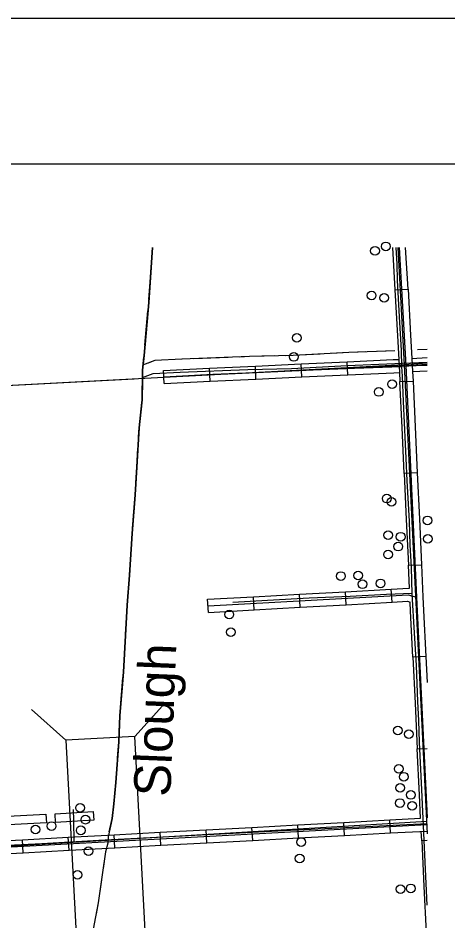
# Model space of a CAD drawing. Extents: x 646058 to 725608, y 1473014 to 1561048.
# Drawn here: x 666031 to 668499, y 1555862 to 1561048 of the extents above; entities that cross this region are included whole.
import ezdxf

# ---------------------------------------------------------------- set-up
doc = ezdxf.new("R2010")
doc.units = 0
for name, color, linetype in [('Default', 7, 'Continuous'), ('R_Border Notes', 7, 'Continuous'), ('T_Vehicle Path Rt', 7, 'Continuous')]:
    doc.layers.add(name, color=color, linetype=linetype)

msp = doc.modelspace()

# ---------------------------------------------------------------- linework, layer by layer
at = {"layer": 'Default'}
for p, q in [((668194.9, 1559486.8), (668269.8, 1559491.1)), ((667133.3, 1558962.1), (667129.8, 1559037)), ((667397, 1558974.4), (667393.5, 1559049.3)), ((667660.7, 1558986.8), (667657.2, 1559061.7)), ((667924.4, 1558999.1), (667920.9, 1559074)), ((666869.6, 1558949.7), (666866.1, 1559024.6)), ((668223.8, 1558960), (668298.7, 1558963.5)), ((668322.9, 1558436), (668248, 1558432.6)), ((668272.3, 1557905.1), (668347.2, 1557908.6)), ((667650.9, 1557664), (667646.7, 1557738.9)), ((667914.5, 1557678.7), (667910.3, 1557753.6)), ((668178.1, 1557693.4), (668173.9, 1557768.2)), ((667123.7, 1557634.7), (667119.5, 1557709.6)), ((667387.3, 1557649.4), (667383.1, 1557724.2)), ((668372.2, 1557381.3), (668297.3, 1557377.7)), ((666701.1, 1556921.1), (666877.5, 1557117.5)), ((666305.7, 1556899.8), (666109.2, 1557076.2)), ((668322.8, 1556850.3), (668379.5, 1556853)), ((668322.8, 1556850.3), (668322.8, 1556850.3)), ((668168.9, 1556367.5), (668164.9, 1556442.4)), ((667114.5, 1556310.9), (667110.4, 1556385.8)), ((667378.1, 1556325), (667374.1, 1556399.9)), ((667641.7, 1556339.2), (667637.7, 1556414.1)), ((667905.3, 1556353.3), (667901.3, 1556428.2)), ((666060, 1556254.2), (666056, 1556329.1)), ((666323.6, 1556268.4), (666319.6, 1556343.3)), ((666587.2, 1556282.6), (666583.2, 1556357.5)), ((666850.8, 1556296.7), (666846.8, 1556371.6)), ((668379.5, 1556324.4), (668348.4, 1556322.9))]:
    msp.add_line(p, q, dxfattribs=at)
for points in [[(666554.7, 1556373.2), (666570.9, 1556451.2), (666581.9, 1556534.9), (666592.8, 1556657.2), (666609.5, 1556891.6), (666615.4, 1557042.4), (666635.7, 1557290.6), (666647.4, 1557501.1), (666658.3, 1557675.8), (666671.4, 1557848.4), (666686, 1558087.9), (666704.2, 1558310.7), (666713.6, 1558469.4), (666726, 1558693.7), (666743.5, 1558855.3), (666745.7, 1558968.2), (666745.7, 1559025), (666754.4, 1559110.1), (666781.3, 1559413.7), (666802.2, 1559731.1)], [(666802.2, 1559731.1), (666781.3, 1559413.7), (666754.4, 1559110.1), (666745.7, 1559025), (666745.7, 1558968.2), (666743.5, 1558855.3), (666726, 1558693.7), (666713.6, 1558469.4), (666704.2, 1558310.7), (666686, 1558087.9), (666671.4, 1557848.4), (666658.3, 1557675.8), (666647.4, 1557501.1), (666635.7, 1557290.6), (666615.4, 1557042.4), (666609.5, 1556891.6), (666592.8, 1556657.2), (666581.9, 1556534.9), (666570.9, 1556451.2)], [(666789, 1559530.9), (666802.2, 1559731.1)], [(668181.1, 1559731.1), (668194.9, 1559486.8)], [(668235, 1559044.3), (668231.9, 1559138.2), (668220.4, 1559331.5), (668209.5, 1559543.3), (668208.1, 1559634.4), (668202, 1559731.1)], [(668211.1, 1559731.1), (668247.5, 1559057.2)], [(668218.7, 1559731.1), (668257.1, 1559052.2), (668318.2, 1557722), (668379.5, 1556455.4)], [(668269.8, 1559491.1), (668256.2, 1559731.1)], [(666782.5, 1559432.1), (666789, 1559530.9)], [(668194.9, 1559486.8), (668209.8, 1559223.3)], [(668269.8, 1559491.1), (668284.7, 1559227.5)], [(666759.6, 1559169.1), (666777.1, 1559366.4)], [(668209.8, 1559223.3), (668217.5, 1559087.9), (668221.3, 1559013)], [(668284.7, 1559227.5), (668292.4, 1559092.2), (668296.2, 1559017.3)], [(668193.4, 1559137.5), (667930.5, 1559126.7), (667610.5, 1559110.2), (667359.8, 1559103.6), (666972.1, 1559088.7), (666817.1, 1559080.5), (666745.7, 1559053.7)], [(668028.6, 1559130.7), (667930.5, 1559126.7), (667830.8, 1559121.6)], [(668193.4, 1559137.5), (668094.5, 1559133.4)], [(668379.5, 1559145.4), (668324, 1559142.9)], [(668379.5, 1559145.4), (668324, 1559142.9)], [(666744.4, 1558905.8), (666745.7, 1558968.2), (666745.7, 1559025), (666753.7, 1559103.4)], [(666973.4, 1559088.8), (666972.1, 1559088.7), (666817.1, 1559080.5), (666778.3, 1559065.9)], [(667237.2, 1559098.9), (667039.4, 1559091.3)], [(667501.1, 1559107.3), (667359.8, 1559103.6), (667303.2, 1559101.4)], [(667764.9, 1559118.2), (667610.5, 1559110.2), (667567.1, 1559109.1)], [(667920.9, 1559074), (668184.6, 1559086.4)], [(668184.6, 1559086.4), (668217.5, 1559087.9)], [(668292.4, 1559092.2), (668379.5, 1559098)], [(668247.5, 1559057.2), (665595.2, 1558916.1)], [(666745.7, 1558983.3), (666807.2, 1559006.4), (666962.3, 1559014.6), (667349.9, 1559029.5), (667600.6, 1559036.1), (667920.7, 1559052.6), (668283.5, 1559067.4), (668379.5, 1559071.7)], [(666866.1, 1559024.6), (667129.8, 1559037)], [(666867.8, 1558987.2), (668257.1, 1559052.2), (668379.5, 1559060.4)], [(666905.1, 1558990), (667149.2, 1559002.4), (667432.7, 1559014.9), (667630.3, 1559023.1), (667963.5, 1559036.6), (668176.6, 1559045.9), (668235, 1559046)], [(667129.8, 1559037), (667393.5, 1559049.3)], [(667393.5, 1559049.3), (667657.2, 1559061.7)], [(667657.2, 1559061.7), (667920.9, 1559074)], [(668379.5, 1559053.1), (668315.7, 1559050.8), (668235, 1559046)], [(668294.5, 1557739.8), (668289.8, 1557894.2), (668282.8, 1558022.7), (668277.7, 1558159), (668264.1, 1558390.2), (668259, 1558521.3), (668255.3, 1558600.5), (668243.7, 1558846.7), (668238.6, 1558990.8), (668235, 1559044.3)], [(668379.5, 1559065.9), (668247.5, 1559057.2)], [(668247.5, 1559057.2), (668379.5, 1556362.3)], [(666698.3, 1558974.8), (665669.9, 1558920.1)], [(667133.3, 1558962.1), (667397, 1558974.4)], [(667397, 1558974.4), (667660.7, 1558986.8)], [(667660.7, 1558986.8), (667924.4, 1558999.1)], [(667924.4, 1558999.1), (668188.1, 1559011.5)], [(668188.1, 1559011.5), (668221.3, 1559013)], [(668221.3, 1559013), (668223.8, 1558960)], [(668296.2, 1559017.3), (668379.5, 1559022.8)], [(668296.2, 1559017.3), (668298.7, 1558963.5)], [(666869.6, 1558949.7), (667133.3, 1558962.1)], [(668235.9, 1558696.3), (668223.8, 1558960)], [(668298.7, 1558963.5), (668310.8, 1558699.8)], [(666723.2, 1558642.9), (666726, 1558693.7), (666741.8, 1558839.9)], [(668248, 1558432.6), (668235.9, 1558696.3)], [(668310.8, 1558699.8), (668322.9, 1558436)], [(666708.2, 1558379.3), (666713.6, 1558469.4), (666719.6, 1558577)], [(668248, 1558432.6), (668260.1, 1558168.9)], [(668322.9, 1558436), (668335.1, 1558172.3)], [(666688.3, 1558116.1), (666704.2, 1558310.7), (666704.3, 1558313.4)], [(668260.1, 1558168.9), (668272.3, 1557905.1)], [(668335.1, 1558172.3), (668347.2, 1557908.6)], [(666677.7, 1557951.4), (666683.7, 1558050.2)], [(666671.7, 1557852.6), (666677.7, 1557951.4)], [(668278.4, 1557772.8), (668272.3, 1557905.1)], [(668347.2, 1557908.6), (668355.7, 1557723.8), (668359.5, 1557645)], [(666652.9, 1557589.3), (666658.3, 1557675.8), (666666.7, 1557786.8)], [(667121.6, 1557672.1), (668270.4, 1557736.1), (668318.2, 1557722)], [(667263.7, 1557693.5), (667462.6, 1557705), (667702.2, 1557717.6), (667937.6, 1557728), (668145.8, 1557739.5), (668294.4, 1557744.8)], [(667383.1, 1557724.2), (667646.7, 1557738.9)], [(667646.7, 1557738.9), (667910.3, 1557753.6)], [(667910.3, 1557753.6), (668173.9, 1557768.2)], [(668173.9, 1557768.2), (668274.8, 1557773.9), (668278.4, 1557772.8)], [(668379.5, 1555953.1), (668349.2, 1556616.2), (668336.7, 1556890), (668331.1, 1557013), (668326.1, 1557122.8), (668317.8, 1557328.6), (668306.9, 1557517.5), (668294.5, 1557739.8)], [(667119.5, 1557709.6), (667383.1, 1557724.2)], [(667650.9, 1557664), (667914.5, 1557678.7)], [(667914.5, 1557678.7), (668178.1, 1557693.4)], [(668178.1, 1557693.4), (668266.1, 1557698.3), (668282.1, 1557693.6)], [(668284.6, 1557641.3), (668282.1, 1557693.6)], [(667123.7, 1557634.7), (667387.3, 1557649.4)], [(667387.3, 1557649.4), (667650.9, 1557664)], [(668297.3, 1557377.7), (668284.6, 1557641.3)], [(668359.5, 1557645), (668372.2, 1557381.3)], [(666637.7, 1557325.7), (666647.4, 1557501.1), (666648.8, 1557523.4)], [(668297.3, 1557377.7), (668310.1, 1557114)], [(668372.2, 1557381.3), (668379.5, 1557232.1)], [(666617, 1557062.5), (666633.2, 1557259.9)], [(668310.1, 1557114), (668322.8, 1556850.3)], [(666602.9, 1556798.9), (666609.5, 1556891.6), (666613.6, 1556996.6)], [(668335.6, 1556586.6), (668322.8, 1556850.3)], [(666581.9, 1556535.8), (666592.8, 1556657.2), (666598.2, 1556733.1)], [(668342.1, 1556451.9), (668335.6, 1556586.6)], [(666347.4, 1556501.5), (666349.4, 1556440.1), (666350.6, 1556316)], [(665732.9, 1556278.3), (668379.5, 1556436.3)], [(666570.9, 1556451.2), (666549.1, 1556346.3), (666546.9, 1556309.9), (666533.8, 1556258.9), (666514.9, 1556126.4), (666490.1, 1555965.5), (666447.9, 1555734)], [(666554.7, 1556373.2), (666570.9, 1556451.2), (666573.4, 1556470.3)], [(667901.3, 1556428.2), (668164.9, 1556442.4)], [(668164.9, 1556442.4), (668342.1, 1556451.9)], [(664476.5, 1556202.7), (665741.1, 1556274.7), (668379.5, 1556416.3)], [(668379.5, 1556420.5), (667910.2, 1556396.6), (667595.5, 1556382.7), (667045.2, 1556354), (666678, 1556333.2), (666494.9, 1556324.3), (666168.3, 1556305.5), (666010.9, 1556296.6), (665815, 1556286.7), (665717.8, 1556282.3)], [(666846.8, 1556371.6), (667110.4, 1556385.8)], [(667110.4, 1556385.8), (667374.1, 1556399.9)], [(667374.1, 1556399.9), (667637.7, 1556414.1)], [(667637.7, 1556414.1), (667901.3, 1556428.2)], [(668358.2, 1556419.4), (668379.5, 1556421.1)], [(665776.5, 1556314.1), (666056, 1556329.1)], [(666056, 1556329.1), (666319.6, 1556343.3)], [(666319.6, 1556343.3), (666583.2, 1556357.5)], [(666583.2, 1556357.5), (666846.8, 1556371.6)], [(667378.1, 1556325), (667641.7, 1556339.2)], [(667641.7, 1556339.2), (667905.3, 1556353.3)], [(667905.3, 1556353.3), (668168.9, 1556367.5)], [(668168.9, 1556367.5), (668379.5, 1556378.8)], [(668348.4, 1556322.9), (668345.7, 1556377)], [(666323.6, 1556268.4), (666587.2, 1556282.6)], [(666587.2, 1556282.6), (666850.8, 1556296.7)], [(666850.8, 1556296.7), (667114.5, 1556310.9)], [(667114.5, 1556310.9), (667378.1, 1556325)], [(668348.4, 1556322.9), (668361.3, 1556059.2)], [(665796.4, 1556240.1), (666060, 1556254.2)], [(666060, 1556254.2), (666323.6, 1556268.4)], [(666534.6, 1556262.1), (666533.8, 1556258.9), (666514.9, 1556126.4), (666490.1, 1555965.5), (666447.9, 1555734), (666418.1, 1555564.3), (666381, 1555330.6), (666338, 1555091.1), (666324.2, 1555000.1), (666292.2, 1554824.6), (666261.6, 1554646.2), (666245.6, 1554525.4), (666238.3, 1554472.2), (666229.6, 1554408.1), (666228.8, 1554258.2), (666236.1, 1554111.1), (666239, 1553956), (666247.7, 1553796.5), (666250.9, 1553749.9)], [(666534.6, 1556262.1), (666533.8, 1556258.9), (666520.3, 1556164.2)], [(666510.7, 1556098.9), (666490.1, 1555965.5), (666478.8, 1555903.5)], [(668361.3, 1556059.2), (668374.2, 1555795.5)]]:
    msp.add_lwpolyline(points, dxfattribs=at)
for points in [[(666305.7, 1556899.8), (666369.4, 1555713.6), (666764.8, 1555734.8), (666701.1, 1556921.1)], [(666246.8, 1556428.4), (666244.1, 1556478.3), (666462.6, 1556490.1), (666465.3, 1556440.2)], [(665975.5, 1556414), (665972.8, 1556463.9), (666191.3, 1556475.8), (666194, 1556425.8)]]:
    msp.add_lwpolyline(points, close=True, dxfattribs=at)
for centre in [(668142.5, 1559737), (668080.3, 1559711.4), (668061, 1559454.9), (668133.1, 1559441.4), (667631.6, 1559211.3), (667614.8, 1559101.8), (668101.6, 1558900.6), (668178.2, 1558945.7), (668147.5, 1558288.1), (668174.6, 1558270.1), (668381.3, 1558163), (668155.6, 1558078.1), (668227.7, 1558069.1), (668383.5, 1558057.5), (668155.3, 1557967.2), (668213.9, 1558012.3), (667884.9, 1557843.4), (667983.5, 1557846.6), (668008.8, 1557796.1), (668112.4, 1557801.3), (667243.9, 1557622.3), (667252.3, 1557521.2), (668211.5, 1556955.8), (668275, 1556935.4), (668216.4, 1556736.1), (668245.9, 1556690.7), (668224.7, 1556626.7), (668285.9, 1556585.9), (666387, 1556512.4), (668223.7, 1556539.3), (668294, 1556523.4), (666223.7, 1556407.5), (666417.7, 1556444.1), (666131.7, 1556387.7), (666391, 1556382.7), (667656.9, 1556315.4), (666435.5, 1556262.9), (667647.8, 1556220.7), (666372, 1556127.1), (668226.6, 1556044.7), (668285.3, 1556049.2)]:
    msp.add_circle(centre, 25, dxfattribs=at)
at = {"layer": 'R_Border Notes'}
msp.add_line((648725.4, 1560211), (716704.1, 1560211), dxfattribs=at)
at = {"layer": 'T_Vehicle Path Rt'}
msp.add_line((646059.2, 1561048.3), (717725.9, 1561048.3), dxfattribs=at)
msp.add_lwpolyline([(646057.8, 1561048.3), (717725.9, 1561048.3), (717725.9, 1515180.7), (646057.8, 1515180.7)], close=True, dxfattribs=at)

# ---------------------------------------------------------------- texts
at = {"layer": 'Default'}
msp.add_text('Slough', height=211.2, rotation=87.7279, dxfattribs=at).set_placement((666905.2, 1556573.3))

doc.saveas('drawing.dxf')
